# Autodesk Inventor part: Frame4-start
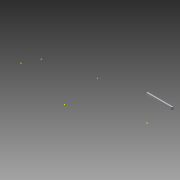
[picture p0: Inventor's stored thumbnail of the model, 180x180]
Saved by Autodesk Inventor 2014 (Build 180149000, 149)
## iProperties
Created: 2009-05
Part Number: Frame4-start
Document SubType Name: Modeling
Designer: millerpa
Density: 1 g/cm^3
Material: Generic
Appearance: Default
Author: millerpa
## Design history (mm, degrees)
derived "Skeleton-frame-start.ipt"
  sketch "Sketch5"
    geometry: L1 (-19.05, -44.45)-(19.05, -44.45) reference; L2 (19.05, -44.45)-(19.05, 44.45) reference; L3 (19.05, 44.45)-(-19.05, 44.45) reference; L4 (-19.05, 44.45)-(-19.05, -44.45) reference; 4 further points
  workplane "Work Plane1"
  workplane "Work Plane2"
  workplane "Work Plane3"
  workplane "Work Plane4"
  workplane "Work Plane5"
  workplane "Work Plane6"
extrude "Extrusion1" new body sketch "Sketch5" stored distance "d4" = 10; taper "d6" = 0 deg
body "Solid1"
feature "Srf3::Skeleton-frame-start.ipt"
body "Srf1"
feature "Srf4::Skeleton-frame-start.ipt"
body "Srf2"
other parameters: "d52" = 45 deg, "d53" = 45 deg, "d0_1" = 3772.27615, "d1" = 914.4, "d2" = 1662.8558, "d26" = 38.1, "d27" = 88.9, "d28" = 19.05, "d29" = 44.45, "d30" = 76.2, "d31" = 127, "d32" = 38.1, "d33" = 88.9, "d34" = 19.05, "d35" = 44.45, "d36" = 76.2, "d37" = 127, "d38" = 38.1, "d39" = 88.9, "d40" = 19.05, "d41" = 44.45, "d42" = 76.2, "d43" = 127, "d44" = 38.1, "d45" = 88.9, "d46" = 19.05, "d47" = 44.45, "d48" = 76.2, "d49" = 127, "d3" = 14.25776, "d5" = 14.25776, "d7" = 14.25776, "d8" = 14.25776, "d9" = 304.8, "d10" = 304.8, "FrameW" = 38.1, "FrameH" = 88.9, "d12" = 38.1, "d13" = 88.9, "d14" = 19.05, "d15" = 44.45, "d16" = 38.1, "d17" = 88.9, "d18" = 19.05, "d19" = 44.45, "d20" = 76.2, "d21" = 127
